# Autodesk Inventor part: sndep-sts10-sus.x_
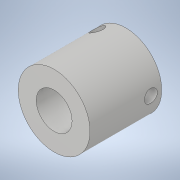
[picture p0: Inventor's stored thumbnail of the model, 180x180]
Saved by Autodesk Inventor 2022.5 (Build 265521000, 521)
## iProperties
Created: 2021-11
Part Number: sndep-sts10-sus.x_
Material: 一般
Document SubType Name: Modeling
Designer: ImaoCorp
Density: 1 g/cm^3
Appearance: 既定
Sending System: SOLIDWORKS 2019-2019304
MC: AMD64
MC_MODEL: Intel64 Family 6 Model 60 Stepping 3, GenuineIntel
OS: Windows_NT
FRU: Parasolid Version 31.0, build 290,  9- 1-2019
FORMAT: text
GUISE: transmit
KEY: sndep-sts10-sus
FILE: sndep-sts10-sus.x_t
DATE: Mon Nov  1 13:02:49 2021
Author: ImaoCorp
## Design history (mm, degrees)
feature "Base1"
node "ソリッド1"
